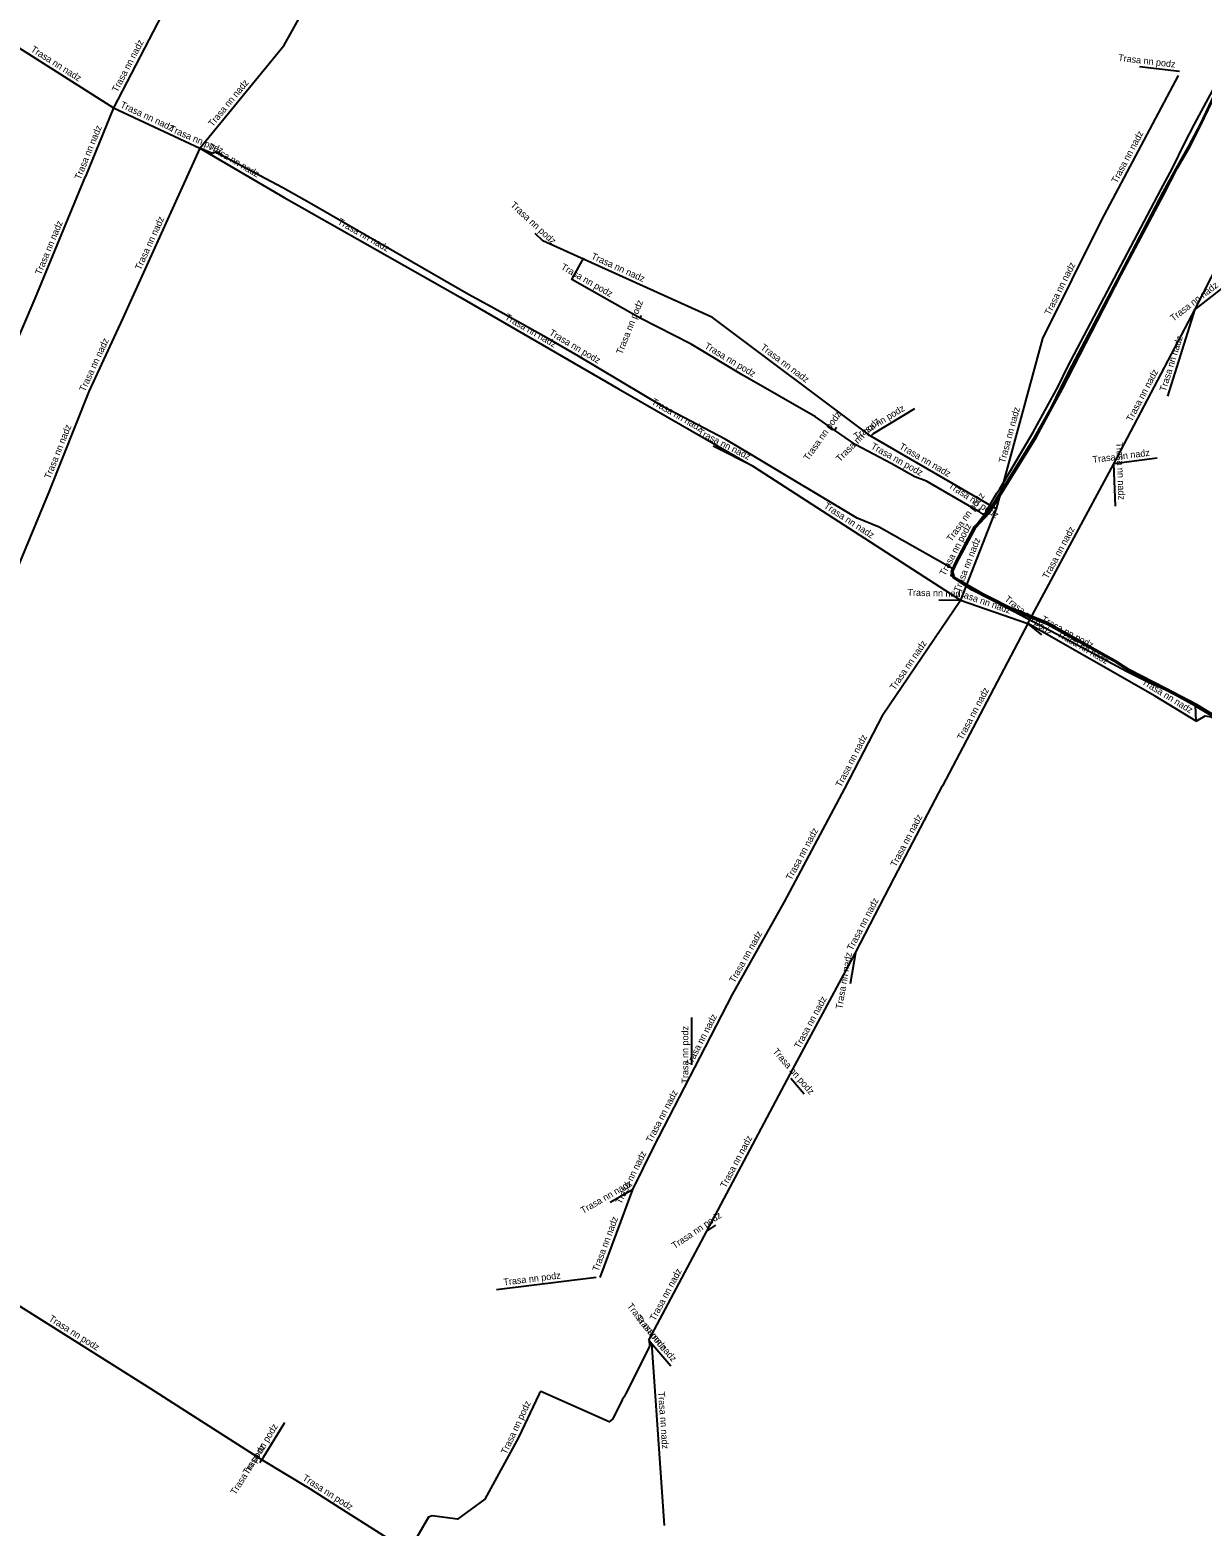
# Model space of a CAD drawing. Extents: x -737281 to -735046, y -1033441 to -1031241.
# Drawn here: x -736080.5 to -735906.4, y -1032757.1 to -1032535 of the extents above; entities that cross this region are included whole.
import ezdxf

# ---------------------------------------------------------------- set-up
doc = ezdxf.new("R2010")
doc.units = 0
for name, color, linetype in [('Level 11', 7, 'Continuous'), ('Level 20', 7, 'Continuous'), ('Level 21', 7, 'Continuous')]:
    doc.layers.add(name, color=color, linetype=linetype)

msp = doc.modelspace()

# ---------------------------------------------------------------- linework, layer by layer
at = {"layer": 'Level 11'}
for p, q in [((-736042.7, -1032537.3), (-736030.1, -1032514.5)), ((-736060.18, -1032531.44), (-736068.06, -1032546.59)), ((-736082.72, -1032537.28), (-736068.06, -1032546.59)), ((-736055.22, -1032552.57), (-736042.7, -1032537.3)), ((-735909.8, -1032541.2), (-735915.7, -1032540.5)), ((-735910, -1032541.8), (-735921.4, -1032563.3)), ((-736068.06, -1032546.59), (-736072.2, -1032556.8)), ((-736068.06, -1032546.59), (-736055.22, -1032552.57)), ((-735907.45, -1032576.44), (-735893.71, -1032549.48)), ((-736055.22, -1032552.57), (-736066.7, -1032577.91)), ((-736053.36, -1032553.38), (-736055.22, -1032552.57)), ((-736055.22, -1032552.57), (-736042.7, -1032559.9)), ((-736079.7, -1032574.9), (-736072.2, -1032556.8)), ((-736042.7, -1032559.9), (-736016.6, -1032574.7)), ((-735921.4, -1032563.3), (-735930.1, -1032580.8)), ((-736005.5, -1032565.2), (-736004.3, -1032566.3)), ((-735979.1, -1032577.7), (-736004.3, -1032566.3)), ((-735903.4, -1032573.3), (-735907.45, -1032576.44)), ((-736087.34, -1032592.71), (-736079.7, -1032574.9)), ((-736016.6, -1032574.7), (-735993.1, -1032588.3)), ((-735919.55, -1032599.41), (-735907.45, -1032576.44)), ((-735911.5, -1032589.4), (-735907.45, -1032576.44)), ((-736066.7, -1032577.91), (-736071.7, -1032588.7)), ((-735989.84, -1032577.82), (-735989.66, -1032577.38)), ((-735955.6, -1032595.3), (-735979.1, -1032577.7)), ((-735930.1, -1032580.8), (-735937.02, -1032606.12)), ((-736071.7, -1032588.7), (-736077.6, -1032603.5)), ((-735993.1, -1032588.3), (-735973.04, -1032599.81)), ((-735955.2, -1032594.9), (-735949.1, -1032591.2)), ((-735961.01, -1032594.41), (-735960.71, -1032593.98)), ((-735955.2, -1032594.9), (-735955.6, -1032595.3)), ((-735937.02, -1032606.12), (-735955.6, -1032595.3)), ((-735973.04, -1032599.81), (-735979, -1032596.8)), ((-735913.1, -1032598.6), (-735919.55, -1032599.41)), ((-735973.04, -1032599.81), (-735942.31, -1032619.67)), ((-735932.29, -1032623.14), (-735919.55, -1032599.41)), ((-735919.3, -1032605.7), (-735919.55, -1032599.41)), ((-736077.6, -1032603.5), (-736084.8, -1032620.8)), ((-735937.02, -1032606.12), (-735942.31, -1032619.67)), ((-735939.68, -1032606.43), (-735939.44, -1032606.1)), ((-735953.9, -1032636.7), (-735942.31, -1032619.67)), ((-735945.5, -1032619.6), (-735942.31, -1032619.67)), ((-735942.31, -1032619.67), (-735932.29, -1032623.14)), ((-735932.29, -1032623.14), (-735944.95, -1032647.2)), ((-735930.2, -1032624.8), (-735932.29, -1032623.14)), ((-735913.4, -1032633.9), (-735932.29, -1032623.14)), ((-735907.32, -1032637.61), (-735913.4, -1032633.9)), ((-735953.9, -1032636.7), (-735959.5, -1032647.6)), ((-735959.5, -1032647.6), (-735968.5, -1032664.4)), ((-735952.1, -1032660.8), (-735944.95, -1032647.2)), ((-735957.9, -1032672), (-735952.1, -1032660.8)), ((-735968.5, -1032664.4), (-735976.2, -1032678.2)), ((-735967.6, -1032690), (-735957.9, -1032672)), ((-735957.9, -1032672), (-735958.7, -1032676.6)), ((-735976.2, -1032678.2), (-735981.78, -1032689.02)), ((-735982.2, -1032688.6), (-735982.2, -1032681.6)), ((-735981.78, -1032689.02), (-735987.9, -1032700.8)), ((-735979.95, -1032713.32), (-735967.6, -1032690)), ((-735967.5, -1032690.6), (-735965.5, -1032692.9)), ((-735987.9, -1032700.8), (-735991, -1032707.1)), ((-735991, -1032707.1), (-735995.83, -1032720.19)), ((-735994.3, -1032709), (-735991, -1032707.1)), ((-735988.55, -1032729.46), (-735979.95, -1032713.32)), ((-735979.95, -1032713.32), (-735978.6, -1032712.4)), ((-735996.4, -1032720.2), (-736011.2, -1032722)), ((-735988.55, -1032729.46), (-735988.2, -1032729.9)), ((-735988.55, -1032729.46), (-735985.3, -1032733.3)), ((-735988.2, -1032729.9), (-735986.3, -1032757)), ((-736046.02, -1032747.23), (-736046.31, -1032747.7))]:
    msp.add_line(p, q, dxfattribs=at)
for points in [[(-735938.65, -1032606.8), (-735937.24, -1032604.35), (-735936.9, -1032603.75), (-735936.45, -1032603.13), (-735931.49, -1032594.73), (-735927.74, -1032587.82), (-735926.42, -1032585.07), (-735912.56, -1032558.75), (-735910.83, -1032555.52), (-735909.01, -1032551.8), (-735907.55, -1032549.02), (-735893.48, -1032522.87)], [(-735943.45, -1032615.02), (-735954.38, -1032608.82), (-735957.66, -1032607.48), (-735973.07, -1032598.24), (-735977.25, -1032595.74), (-735986.47, -1032590.9), (-735999.01, -1032583.46), (-736003.74, -1032580.74), (-736011.99, -1032576.12), (-736015.33, -1032574.27), (-736038.93, -1032560.7), (-736042.93, -1032558.47), (-736052.9, -1032553.17), (-736053.36, -1032553.38)], [(-735989.84, -1032577.82), (-735999.99, -1032572.04), (-735998.21, -1032568.84)], [(-735961.01, -1032594.41), (-735963.85, -1032592.42), (-735974.73, -1032586.19), (-735982.31, -1032581.65), (-735989.84, -1032577.82)], [(-735939.68, -1032606.43), (-735947.33, -1032602.01), (-735949.07, -1032601.36), (-735952.6, -1032599.39), (-735957.86, -1032596.6), (-735961.01, -1032594.41)], [(-735943.45, -1032615.02), (-735940.17, -1032608.76), (-735938.65, -1032606.8)], [(-735939.68, -1032606.43), (-735939.09, -1032606.82), (-735938.81, -1032606.86), (-735938.65, -1032606.8)], [(-735907.32, -1032637.61), (-735907.43, -1032635.29), (-735911.89, -1032632.94), (-735914.5, -1032631.82), (-735917.65, -1032630.24), (-735925.2, -1032626.17), (-735935.26, -1032620.91), (-735940.18, -1032618.02), (-735943.66, -1032616.04), (-735943.45, -1032615.02)], [(-735907.32, -1032637.61), (-735905.98, -1032636.84), (-735905.06, -1032636.97), (-735894.16, -1032643.39)], [(-736046.02, -1032747.23), (-736057.95, -1032739.63), (-736062.51, -1032736.72), (-736075.1, -1032728.79), (-736088.27, -1032720.54), (-736092.49, -1032717.79), (-736099.44, -1032713.46)], [(-735988.55, -1032729.46), (-735988.46, -1032729.96), (-735988.45, -1032730.43), (-735991.98, -1032737.38), (-735992.23, -1032737.87), (-735992.52, -1032738.35), (-735993.9, -1032741.15), (-735994.44, -1032741.59), (-736004.59, -1032737.11), (-736004.87, -1032737.43), (-736007.93, -1032743.94), (-736012.91, -1032753.1), (-736016.99, -1032756.02), (-736020.75, -1032755.53), (-736021.28, -1032755.77), (-736024.14, -1032760.7), (-736024.37, -1032761.13)], [(-736042.67, -1032741.69), (-736042.93, -1032742.13), (-736045.85, -1032746.9), (-736046.02, -1032747.23)], [(-736024.37, -1032761.13), (-736025.5, -1032760.07), (-736034.38, -1032754.42), (-736038.82, -1032751.58), (-736046.02, -1032747.23)]]:
    msp.add_lwpolyline(points, dxfattribs=at)
at = {"layer": 'Level 21'}
for points in [[(-735892.61, -1032644.31), (-735907.39, -1032635.36), (-735911.92, -1032632.92), (-735917.38, -1032630.04), (-735919.19, -1032628.9), (-735929.45, -1032623.24), (-735935.2, -1032620.91), (-735940.56, -1032618.16), (-735943.36, -1032616.36), (-735943.63, -1032615.41), (-735943.05, -1032614.06), (-735940.23, -1032608.7), (-735938.21, -1032606.6), (-735931.27, -1032595.43), (-735928.81, -1032590.99), (-735927.42, -1032588.14), (-735925.73, -1032584.83), (-735918.58, -1032571.32), (-735912.19, -1032559.12), (-735910.3, -1032555.58), (-735908.41, -1032552.25), (-735906.65, -1032549), (-735901.73, -1032538.54)], [(-735892.44, -1032644.08), (-735907.26, -1032635.14), (-735911.79, -1032632.77), (-735917.29, -1032629.92), (-735919.12, -1032628.76), (-735929.45, -1032622.95), (-735935.06, -1032620.69), (-735940.4, -1032617.97), (-735943.2, -1032616.27), (-735943.42, -1032615.39), (-735942.83, -1032614.12), (-735940, -1032608.86), (-735938.01, -1032606.67), (-735931.07, -1032595.51), (-735928.66, -1032591.01), (-735927.15, -1032588.27), (-735925.48, -1032585), (-735918.46, -1032571.38), (-735912.15, -1032559.53), (-735910.13, -1032555.58), (-735908.23, -1032552.35), (-735906.55, -1032549.04), (-735901.42, -1032538.27)]]:
    msp.add_lwpolyline(points, dxfattribs=at)

# ---------------------------------------------------------------- texts
at = {"layer": 'Level 20'}
for s, rotation, p in [('Trasa nn nadz', 62.5196, (-736067.47, -1032544.36)), ('Trasa nn nadz', 327.5819, (-736080.43, -1032538.14)), ('Trasa nn podz', 353.2338, (-735918.93, -1032539.61)), ('Trasa nn nadz', 50.6514, (-736053.33, -1032549.48)), ('Trasa nn nadz', 335.0271, (-736067.13, -1032546.47)), ('Trasa nn nadz', 67.9282, (-736072.96, -1032557.33)), ('Trasa nn podz', 336.4677, (-736059.85, -1032550.01)), ('Trasa nn nadz', 62.066, (-735919.09, -1032557.87)), ('Trasa nn nadz', 329.6526, (-736054.13, -1032552.63)), ('Trasa nn podz', 317.4896, (-736009.2, -1032561.13)), ('Trasa nn nadz', 67.4926, (-736078.82, -1032571.47)), ('Trasa nn nadz', 65.6276, (-736064.01, -1032570.76)), ('Trasa nn nadz', 330.4446, (-736034.87, -1032563.76)), ('Trasa nn podz', 330.3226, (-736001.72, -1032570.48)), ('Trasa nn nadz', 335.6589, (-735997.22, -1032568.95)), ('Trasa nn nadz', 63.5661, (-735929, -1032577.46)), ('Trasa nn nadz', 37.7867, (-735910.7, -1032578.33)), ('Trasa nn podz', 68.287, (-735992.54, -1032583.26)), ('Trasa nn nadz', 329.941, (-736010.04, -1032577.92)), ('Trasa nn nadz', 65.1374, (-736072.3, -1032588.8)), ('Trasa nn podz', 329.3193, (-736003.47, -1032580.23)), ('Trasa nn nadz', 72.646, (-735911.83, -1032588.77)), ('Trasa nn podz', 329.1008, (-735980.41, -1032582.2)), ('Trasa nn nadz', 323.1691, (-735972.08, -1032582.33)), ('Trasa nn nadz', 62.22, (-735916.87, -1032593.25)), ('Trasa nn nadz', 330.1537, (-735988.27, -1032590.49)), ('Trasa nn podz', 54.7824, (-735964.89, -1032599.04)), ('Trasa nn podz', 31.2392, (-735957.78, -1032595.88)), ('Trasa nn nadz', 74.716, (-735935.7, -1032599.39)), ('Trasa nn nadz', 68.2654, (-736077.44, -1032601.76)), ('Trasa nn nadz', 333.2047, (-735981.41, -1032595.02)), ('Trasa nn podz', 45, (-735960.2, -1032599.19)), ('Trasa nn podz', 330.845, (-735955.69, -1032597.09)), ('Trasa nn nadz', 329.7789, (-735951.49, -1032597.11)), ('Trasa nn nadz', 272.2855, (-735919.18, -1032596.25)), ('Trasa nn nadz', 7.1655, (-735922.63, -1032599.29)), ('Trasa nn podz', 326.6664, (-735944.18, -1032602.87)), ('Trasa nn nadz', 327.1187, (-735962.68, -1032605.91)), ('Trasa nn podz', 54.1372, (-735943.65, -1032611.06)), ('Trasa nn podz', 62.3472, (-735944.6, -1032616.13)), ('Trasa nn nadz', 61.7782, (-735929.33, -1032616.58)), ('Trasa nn nadz', 68.6645, (-735942.42, -1032618.57)), ('Trasa nn nadz', 358.6699, (-735950.18, -1032618.99)), ('Trasa nn nadz', 340.9314, (-735943.08, -1032618.88)), ('Trasa nn podz', 321.4879, (-735935.85, -1032619.66)), ('Trasa nn podz', 331.6721, (-735930.41, -1032622.79)), ('Trasa nn nadz', 330.3284, (-735928.06, -1032624.97)), ('Trasa nn nadz', 55.7629, (-735952.06, -1032633.1)), ('Trasa nn nadz', 328.6128, (-735915.47, -1032632.05)), ('Trasa nn nadz', 62.2474, (-735941.99, -1032640.5)), ('Trasa nn nadz', 62.8076, (-735960.02, -1032647.51)), ('Trasa nn nadz', 62.2541, (-735951.89, -1032659.33)), ('Trasa nn nadz', 61.8214, (-735967.41, -1032661.31)), ('Trasa nn nadz', 62.6223, (-735958.34, -1032671.75)), ('Trasa nn nadz', 60.8397, (-735975.85, -1032676.55)), ('Trasa nn nadz', 80.1342, (-735959.87, -1032680.41)), ('Trasa nn nadz', 61.6803, (-735966.17, -1032686.3)), ('Trasa nn podz', 90, (-735982.7, -1032691.39)), ('Trasa nn nadz', 62.7317, (-735982.31, -1032688.97)), ('Trasa nn podz', 311.0091, (-735970.25, -1032686.68)), ('Trasa nn nadz', 62.5357, (-735988.18, -1032700.26)), ('Trasa nn nadz', 62.0965, (-735977.16, -1032706.98)), ('Trasa nn nadz', 63.7999, (-735992.67, -1032709.37)), ('Trasa nn nadz', 29.9315, (-735998.35, -1032710.75)), ('Trasa nn nadz', 69.7611, (-735996.06, -1032719.37)), ('Trasa nn podz', 34.2169, (-735984.75, -1032715.98)), ('Trasa nn podz', 6.9343, (-736010.1, -1032721.36)), ('Trasa nn nadz', 61.9528, (-735987.65, -1032726.7)), ('Trasa nn podz', 308.3408, (-735991.88, -1032724.44)), ('Trasa nn podz', 327.7999, (-736077.76, -1032726.52)), ('Trasa nn nadz', 310.2257, (-735990.6, -1032726.26)), ('Trasa nn podz', 64.834, (-736009.69, -1032746.51)), ('Trasa nn nadz', 274.0105, (-735987.19, -1032737.14)), ('Trasa nn podz', 58.4771, (-736048.07, -1032749.55)), ('Trasa nn podz', 57.9946, (-736049.93, -1032752.53)), ('Trasa nn podz', 327.3496, (-736040.08, -1032750.17))]:
    msp.add_text(s, height=1, rotation=rotation, dxfattribs=at).set_placement(p)

doc.saveas('drawing.dxf')
